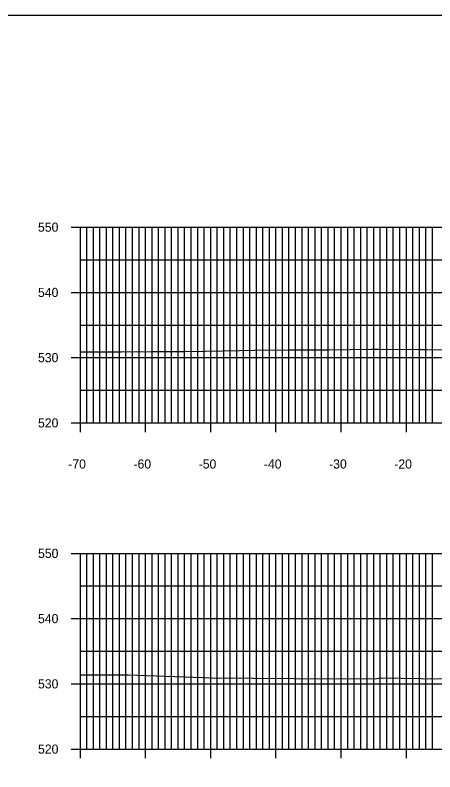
# Model space of a CAD drawing. Extents: x 1509063 to 1512863, y 401160 to 402918.
# Drawn here: x 1512342.7 to 1512407.1, y 402346.1 to 402462.1 of the extents above; entities that cross this region are included whole.
import ezdxf

# ---------------------------------------------------------------- set-up
doc = ezdxf.new("R2010")
doc.units = 0
for name, color, linetype in [('NBL1', 7, 'Continuous'), ('XAX_P', 7, 'Continuous'), ('XAXTIC_P', 7, 'Continuous'), ('XAXTXT_P_T', 7, 'Continuous'), ('XGL_P', 7, 'Continuous'), ('XSLOG', 7, 'Continuous')]:
    doc.layers.add(name, color=color, linetype=linetype)

msp = doc.modelspace()

# ---------------------------------------------------------------- linework, layer by layer
at = {"layer": 'NBL1'}
msp.add_lwpolyline([(1512502.73, 402252.08), (1512182.73, 402252.08), (1512182.73, 402462.08), (1512502.73, 402462.08)], close=True, dxfattribs=at)
at = {"layer": 'XAX_P'}
for p, q in [((1512352.73, 402399.58), (1512352.73, 402429.58)), ((1512352.73, 402399.58), (1512492.73, 402399.58)), ((1512352.73, 402349.58), (1512352.73, 402379.58)), ((1512352.73, 402349.58), (1512492.73, 402349.58))]:
    msp.add_line(p, q, dxfattribs=at)
at = {"layer": 'XAXTIC_P'}
for p, q in [((1512351.33, 402429.58), (1512354.13, 402429.58)), ((1512351.33, 402419.58), (1512354.13, 402419.58)), ((1512351.33, 402409.58), (1512354.13, 402409.58)), ((1512352.73, 402398.18), (1512352.73, 402400.98)), ((1512362.73, 402398.18), (1512362.73, 402400.98)), ((1512372.73, 402398.18), (1512372.73, 402400.98)), ((1512382.73, 402398.18), (1512382.73, 402400.98)), ((1512392.73, 402398.18), (1512392.73, 402400.98)), ((1512402.73, 402398.18), (1512402.73, 402400.98)), ((1512351.33, 402399.58), (1512354.13, 402399.58)), ((1512351.33, 402379.58), (1512354.13, 402379.58)), ((1512351.33, 402369.58), (1512354.13, 402369.58)), ((1512351.33, 402359.58), (1512354.13, 402359.58)), ((1512352.73, 402348.18), (1512352.73, 402350.98)), ((1512362.73, 402348.18), (1512362.73, 402350.98)), ((1512372.73, 402348.18), (1512372.73, 402350.98)), ((1512382.73, 402348.18), (1512382.73, 402350.98)), ((1512392.73, 402348.18), (1512392.73, 402350.98)), ((1512402.73, 402348.18), (1512402.73, 402350.98)), ((1512351.33, 402349.58), (1512354.13, 402349.58))]:
    msp.add_line(p, q, dxfattribs=at)
at = {"layer": 'XGL_P'}
for p, q in [((1512352.73, 402429.58), (1512492.73, 402429.58)), ((1512352.73, 402399.58), (1512352.73, 402429.58)), ((1512353.73, 402399.58), (1512353.73, 402429.58)), ((1512354.73, 402399.58), (1512354.73, 402429.58)), ((1512355.73, 402399.58), (1512355.73, 402429.58)), ((1512356.73, 402399.58), (1512356.73, 402429.58)), ((1512357.73, 402399.58), (1512357.73, 402429.58)), ((1512358.73, 402399.58), (1512358.73, 402429.58)), ((1512359.73, 402399.58), (1512359.73, 402429.58)), ((1512360.73, 402399.58), (1512360.73, 402429.58)), ((1512361.73, 402399.58), (1512361.73, 402429.58)), ((1512362.73, 402399.58), (1512362.73, 402429.58)), ((1512363.73, 402399.58), (1512363.73, 402429.58)), ((1512364.73, 402399.58), (1512364.73, 402429.58)), ((1512365.73, 402399.58), (1512365.73, 402429.58)), ((1512366.73, 402399.58), (1512366.73, 402429.58)), ((1512367.73, 402399.58), (1512367.73, 402429.58)), ((1512368.73, 402399.58), (1512368.73, 402429.58)), ((1512369.73, 402399.58), (1512369.73, 402429.58)), ((1512370.73, 402399.58), (1512370.73, 402429.58)), ((1512371.73, 402399.58), (1512371.73, 402429.58)), ((1512372.73, 402399.58), (1512372.73, 402429.58)), ((1512373.73, 402399.58), (1512373.73, 402429.58)), ((1512374.73, 402399.58), (1512374.73, 402429.58)), ((1512375.73, 402399.58), (1512375.73, 402429.58)), ((1512376.73, 402399.58), (1512376.73, 402429.58)), ((1512377.73, 402399.58), (1512377.73, 402429.58)), ((1512378.73, 402399.58), (1512378.73, 402429.58)), ((1512379.73, 402399.58), (1512379.73, 402429.58)), ((1512380.73, 402399.58), (1512380.73, 402429.58)), ((1512381.73, 402399.58), (1512381.73, 402429.58)), ((1512382.73, 402399.58), (1512382.73, 402429.58)), ((1512383.73, 402399.58), (1512383.73, 402429.58)), ((1512384.73, 402399.58), (1512384.73, 402429.58)), ((1512385.73, 402399.58), (1512385.73, 402429.58)), ((1512386.73, 402399.58), (1512386.73, 402429.58)), ((1512387.73, 402399.58), (1512387.73, 402429.58)), ((1512388.73, 402399.58), (1512388.73, 402429.58)), ((1512389.73, 402399.58), (1512389.73, 402429.58)), ((1512390.73, 402399.58), (1512390.73, 402429.58)), ((1512391.73, 402399.58), (1512391.73, 402429.58)), ((1512392.73, 402399.58), (1512392.73, 402429.58)), ((1512393.73, 402399.58), (1512393.73, 402429.58)), ((1512394.73, 402399.58), (1512394.73, 402429.58)), ((1512395.73, 402399.58), (1512395.73, 402429.58)), ((1512396.73, 402399.58), (1512396.73, 402429.58)), ((1512397.73, 402399.58), (1512397.73, 402429.58)), ((1512398.73, 402399.58), (1512398.73, 402429.58)), ((1512399.73, 402399.58), (1512399.73, 402429.58)), ((1512400.73, 402399.58), (1512400.73, 402429.58)), ((1512401.73, 402399.58), (1512401.73, 402429.58)), ((1512402.73, 402399.58), (1512402.73, 402429.58)), ((1512403.73, 402399.58), (1512403.73, 402429.58)), ((1512404.73, 402399.58), (1512404.73, 402429.58)), ((1512405.73, 402399.58), (1512405.73, 402429.58)), ((1512406.73, 402399.58), (1512406.73, 402429.58)), ((1512352.73, 402424.58), (1512492.73, 402424.58)), ((1512352.73, 402419.58), (1512492.73, 402419.58)), ((1512352.73, 402414.58), (1512492.73, 402414.58)), ((1512352.73, 402409.58), (1512492.73, 402409.58)), ((1512352.73, 402404.58), (1512492.73, 402404.58)), ((1512352.73, 402399.58), (1512492.73, 402399.58)), ((1512352.73, 402379.58), (1512492.73, 402379.58)), ((1512352.73, 402349.58), (1512352.73, 402379.58)), ((1512353.73, 402349.58), (1512353.73, 402379.58)), ((1512354.73, 402349.58), (1512354.73, 402379.58)), ((1512355.73, 402349.58), (1512355.73, 402379.58)), ((1512356.73, 402349.58), (1512356.73, 402379.58)), ((1512357.73, 402349.58), (1512357.73, 402379.58)), ((1512358.73, 402349.58), (1512358.73, 402379.58)), ((1512359.73, 402349.58), (1512359.73, 402379.58)), ((1512360.73, 402349.58), (1512360.73, 402379.58)), ((1512361.73, 402349.58), (1512361.73, 402379.58)), ((1512362.73, 402349.58), (1512362.73, 402379.58)), ((1512363.73, 402349.58), (1512363.73, 402379.58)), ((1512364.73, 402349.58), (1512364.73, 402379.58)), ((1512365.73, 402349.58), (1512365.73, 402379.58)), ((1512366.73, 402349.58), (1512366.73, 402379.58)), ((1512367.73, 402349.58), (1512367.73, 402379.58)), ((1512368.73, 402349.58), (1512368.73, 402379.58)), ((1512369.73, 402349.58), (1512369.73, 402379.58)), ((1512370.73, 402349.58), (1512370.73, 402379.58)), ((1512371.73, 402349.58), (1512371.73, 402379.58)), ((1512372.73, 402349.58), (1512372.73, 402379.58)), ((1512373.73, 402349.58), (1512373.73, 402379.58)), ((1512374.73, 402349.58), (1512374.73, 402379.58)), ((1512375.73, 402349.58), (1512375.73, 402379.58)), ((1512376.73, 402349.58), (1512376.73, 402379.58)), ((1512377.73, 402349.58), (1512377.73, 402379.58)), ((1512378.73, 402349.58), (1512378.73, 402379.58)), ((1512379.73, 402349.58), (1512379.73, 402379.58)), ((1512380.73, 402349.58), (1512380.73, 402379.58)), ((1512381.73, 402349.58), (1512381.73, 402379.58)), ((1512382.73, 402349.58), (1512382.73, 402379.58)), ((1512383.73, 402349.58), (1512383.73, 402379.58)), ((1512384.73, 402349.58), (1512384.73, 402379.58)), ((1512385.73, 402349.58), (1512385.73, 402379.58)), ((1512386.73, 402349.58), (1512386.73, 402379.58)), ((1512387.73, 402349.58), (1512387.73, 402379.58)), ((1512388.73, 402349.58), (1512388.73, 402379.58)), ((1512389.73, 402349.58), (1512389.73, 402379.58)), ((1512390.73, 402349.58), (1512390.73, 402379.58)), ((1512391.73, 402349.58), (1512391.73, 402379.58)), ((1512392.73, 402349.58), (1512392.73, 402379.58)), ((1512393.73, 402349.58), (1512393.73, 402379.58)), ((1512394.73, 402349.58), (1512394.73, 402379.58)), ((1512395.73, 402349.58), (1512395.73, 402379.58)), ((1512396.73, 402349.58), (1512396.73, 402379.58)), ((1512397.73, 402349.58), (1512397.73, 402379.58)), ((1512398.73, 402349.58), (1512398.73, 402379.58)), ((1512399.73, 402349.58), (1512399.73, 402379.58)), ((1512400.73, 402349.58), (1512400.73, 402379.58)), ((1512401.73, 402349.58), (1512401.73, 402379.58)), ((1512402.73, 402349.58), (1512402.73, 402379.58)), ((1512403.73, 402349.58), (1512403.73, 402379.58)), ((1512404.73, 402349.58), (1512404.73, 402379.58)), ((1512405.73, 402349.58), (1512405.73, 402379.58)), ((1512406.73, 402349.58), (1512406.73, 402379.58)), ((1512352.73, 402374.58), (1512492.73, 402374.58)), ((1512352.73, 402369.58), (1512492.73, 402369.58)), ((1512352.73, 402364.58), (1512492.73, 402364.58)), ((1512352.73, 402359.58), (1512492.73, 402359.58)), ((1512352.73, 402354.58), (1512492.73, 402354.58)), ((1512352.73, 402349.58), (1512492.73, 402349.58))]:
    msp.add_line(p, q, dxfattribs=at)
at = {"layer": 'XSLOG'}
for points in [[(1512352.73, 402410.45), (1512353.04, 402410.45), (1512354.09, 402410.46), (1512359.01, 402410.48), (1512363.66, 402410.51), (1512364.98, 402410.52), (1512368.64, 402410.54), (1512371.88, 402410.56), (1512377.16, 402410.7), (1512379.37, 402410.72), (1512384.85, 402410.76), (1512390.88, 402410.76), (1512397.28, 402410.86), (1512398.31, 402410.88), (1512398.39, 402410.88), (1512398.45, 402410.88), (1512404.61, 402410.82), (1512405.89, 402410.81), (1512409.07, 402410.78)], [(1512352.73, 402360.97), (1512360.04, 402360.95), (1512372.97, 402360.5), (1512391.76, 402360.36), (1512398.22, 402360.38), (1512398.8, 402360.48), (1512404.99, 402360.41), (1512409.91, 402360.35), (1512409.98, 402360.35), (1512422.76, 402360.86), (1512434.12, 402360.66), (1512434.34, 402360.65), (1512437.3, 402360.81), (1512437.99, 402360.85), (1512438.82, 402360.95), (1512441.51, 402361.07), (1512453.39, 402361.7), (1512453.48, 402361.69), (1512457.86, 402361.94), (1512476.8, 402362.56), (1512482.52, 402362.86), (1512492.73, 402363.09)]]:
    msp.add_lwpolyline(points, dxfattribs=at)

# ---------------------------------------------------------------- texts
at = {"layer": 'XAXTXT_P_T'}
for s, p in [('550', (1512346.24, 402428.88)), ('540', (1512346.24, 402418.88)), ('530', (1512346.24, 402408.88)), ('520', (1512346.24, 402398.88)), ('-70', (1512350.88, 402392.58)), ('-60', (1512360.88, 402392.58)), ('-50', (1512370.88, 402392.58)), ('-40', (1512380.88, 402392.58)), ('-30', (1512390.88, 402392.58)), ('-20', (1512400.88, 402392.58)), ('550', (1512346.24, 402378.88)), ('540', (1512346.24, 402368.88)), ('530', (1512346.24, 402358.88)), ('520', (1512346.24, 402348.88))]:
    msp.add_text(s, height=1.4, dxfattribs=at).set_placement(p)

doc.saveas('drawing.dxf')
